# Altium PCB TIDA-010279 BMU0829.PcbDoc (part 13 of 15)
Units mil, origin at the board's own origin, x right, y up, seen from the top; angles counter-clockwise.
Board outline 11269.69 x 4438.98 mil, 4 copper layers (Top Layer, Signal Layer 1, Signal Layer 2, Bottom Layer), stack 61.6 mil thick; 1494 components, 725 nets, 3766 pads, 2728 vias.
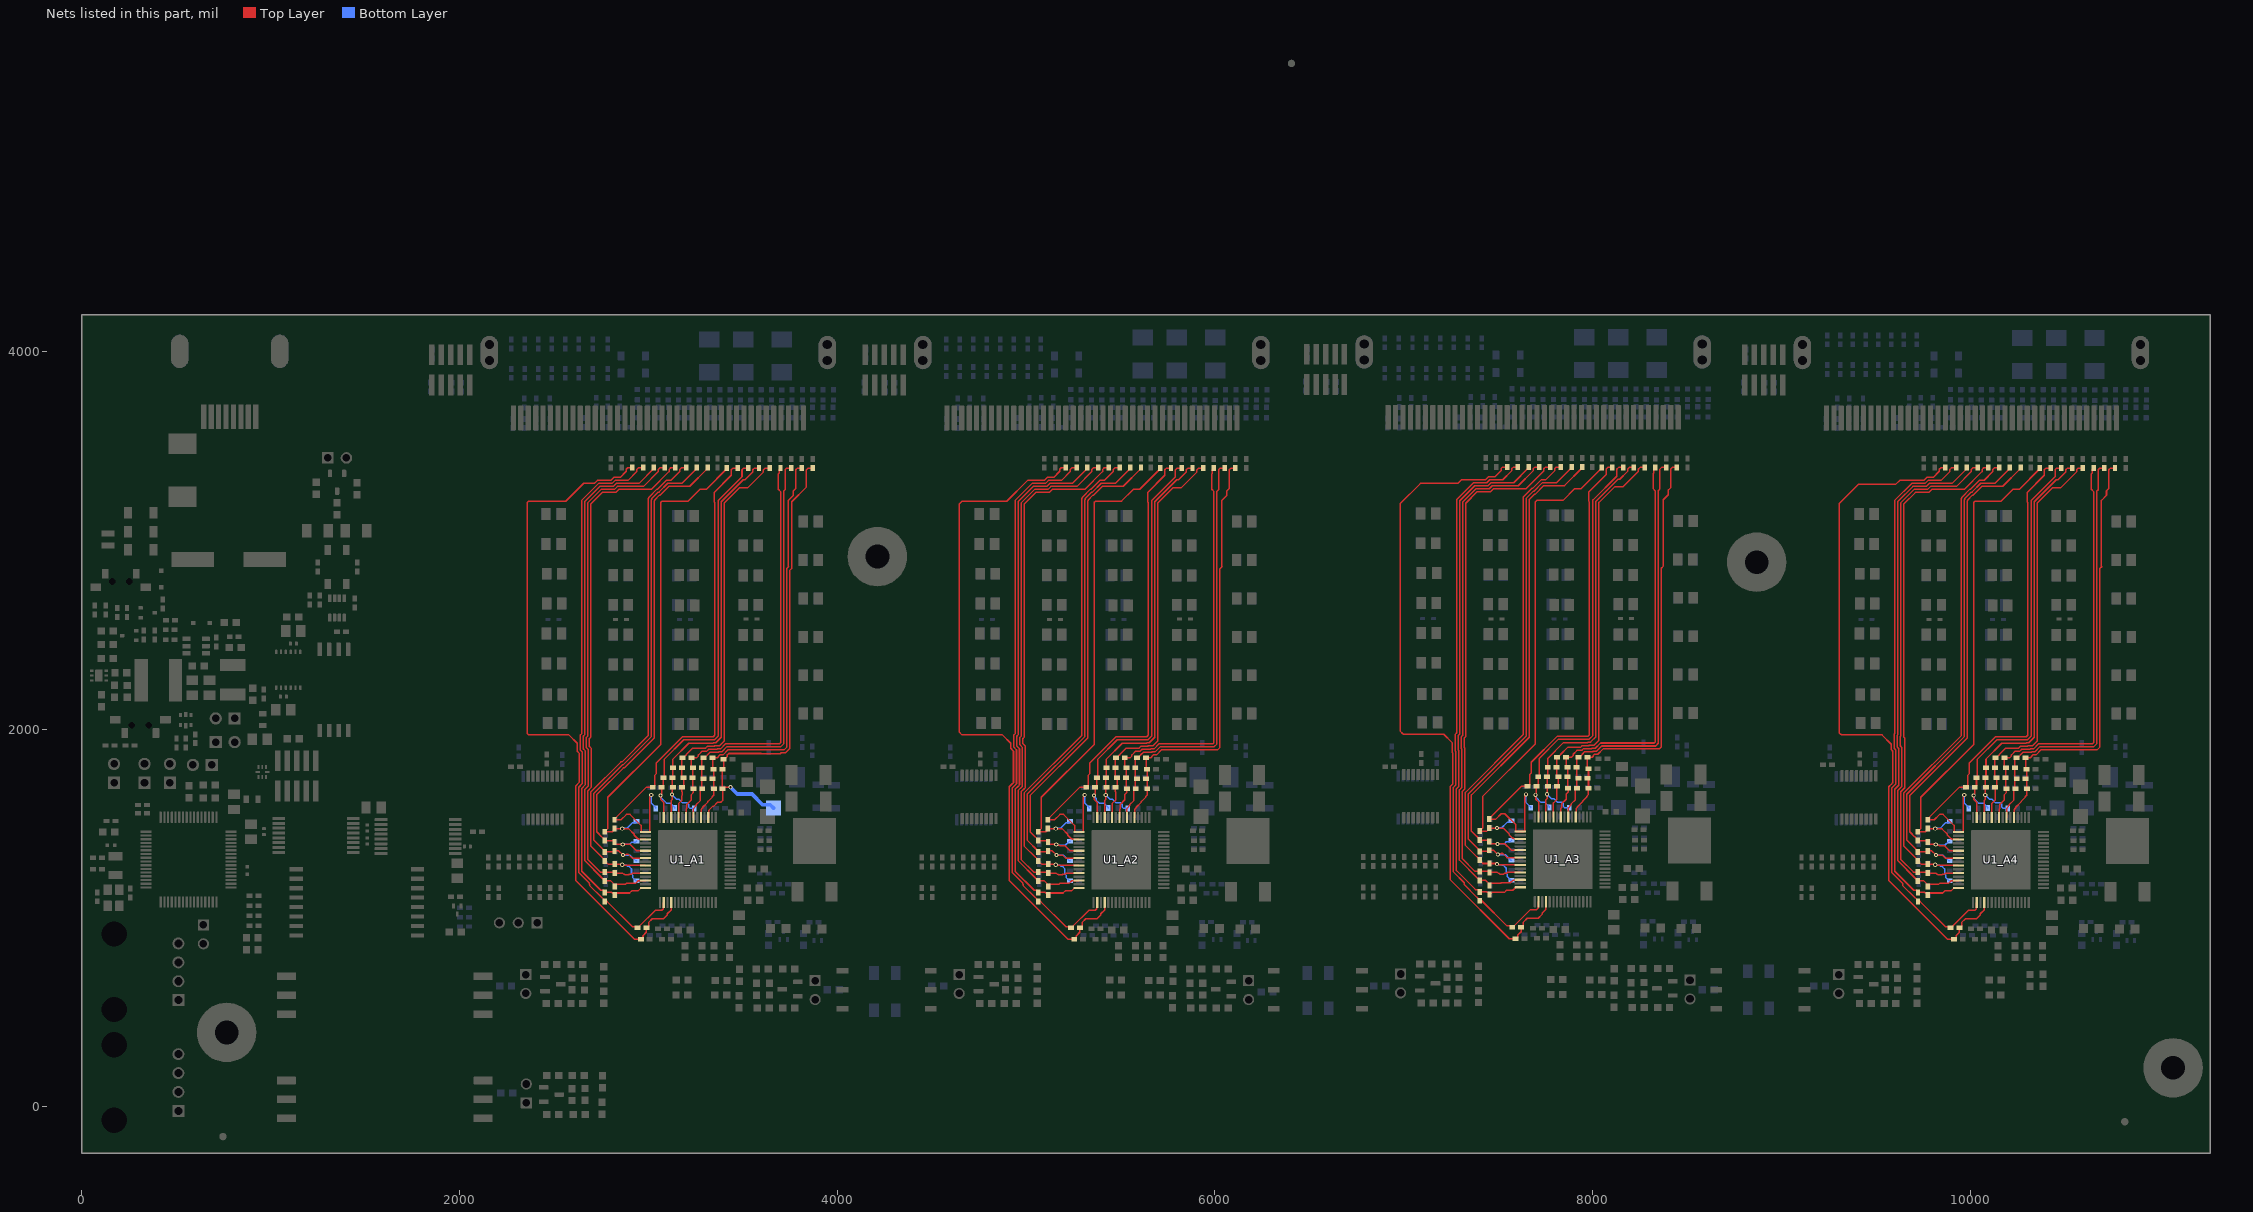
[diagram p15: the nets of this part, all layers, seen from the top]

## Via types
v1: diameter 22.01, hole 12.01, Top Layer to Bottom Layer, tented both sides, 2578 vias
v2: diameter 19.68, hole 7.87, Top Layer to Bottom Layer, tented both sides, 144 vias
v3: diameter 92.52, hole 49.21, Top Layer to Bottom Layer, 4 vias
v4: diameter 19.68, hole 7.87, Top Layer to Bottom Layer, 2 vias

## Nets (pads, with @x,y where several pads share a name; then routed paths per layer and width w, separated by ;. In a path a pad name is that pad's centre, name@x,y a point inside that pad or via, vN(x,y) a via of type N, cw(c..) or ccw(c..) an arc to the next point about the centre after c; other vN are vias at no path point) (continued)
VC2_A1: C104_A1.2 C105_A1.1 R135_A1.2 U1_A1.36 | length 3663.8
  Top Layer w8: R135_A1.2@2915.31,3384.01 2891.5,3384.01 2883.33,3375.85 2883.33,3364.55 2851.42,3332.64 2817,3332.64 2801.13,3316.77 2730.13,3316.77 2714.43,3301.07 2657.48,3301.07 2562.88,3206.46 2365.95,3206.46 2359,3199.51 2359,3002.59 2358.99,1976.1 2366.15,1968.94 2579.82,1968.94 2623.51,1925.25 2623.51,1882.87 2633.36,1873.02 2633.36,1717.29 2615.26,1699.19 2615.26,1198.42 2926.49,887.19 C105_A1.1@2952.76,887.19 ; C105_A1.1@2952.76,885.83 2962.54,885.83 2971.72,895 2971.72,906.42 2989.45,924.15 C104_A1.2@2989.45,947.96 2993.39,947.96 3001.2,955.77 3001.2,975.34 3021.25,995.39 3079.89,995.39 3100.39,1015.88 3100.39,1022.22 3120.88,1042.72 U1_A1.36@3120.88,1082.55 ; C105_A1.1@2959.97,887.19 C105_A1.1@2961.33,885.83
VC2_A2: C104_A2.2 C105_A2.1 R135_A2.2 U1_A2.36 | length 3674.9
  Top Layer w8: R135_A2.2@5210.32,3384.01 5186.51,3384.01 5178.35,3375.85 5178.35,3364.55 5146.44,3332.64 5112.02,3332.64 5096.15,3316.77 5008.13,3316.77 4897.83,3206.46 4660.97,3206.46 4645.67,3191.16 4645.67,1984.43 4661.17,1968.94 4874.84,1968.94 4918.53,1925.25 4918.53,1898.02 4933.32,1883.23 4933.32,1717.21 4926.66,1710.55 4910.28,1694.16 4910.28,1198.42 5221.51,887.19 C105_A2.1@5247.77,887.19 ; C105_A2.1@5247.77,885.83 5257.56,885.83 5266.73,895 5266.73,906.42 5284.47,924.15 C104_A2.2@5284.47,947.96 5288.4,947.96 5296.22,955.77 5296.22,975.34 5316.27,995.39 5374.91,995.39 5395.4,1015.88 5395.4,1022.22 5415.9,1042.72 U1_A2.36@5415.9,1082.55 ; C105_A2.1@5254.99,887.19 C105_A2.1@5256.35,885.83
VC2_A3: C104_A3.2 C105_A3.1 R135_A3.2 U1_A3.36 | length 3664.9
  Top Layer w8: R135_A3.2@7546.92,3387.22 7523.11,3387.22 7514.95,3379.06 7514.95,3367.76 7483.04,3335.85 7448.62,3335.85 7432.74,3319.98 7304.79,3319.98 7285.16,3300.34 7087.72,3300.34 6980.2,3192.82 6980.2,1989.64 6993.96,1975.87 6994.04,1975.87 6997.76,1972.15 7211.44,1972.15 7255.12,1928.46 7255.12,1877.23 7259.34,1873.02 7259.34,1709.84 7246.87,1697.37 7246.87,1201.63 7558.1,890.4 C105_A3.1@7591.58,890.4 ; C105_A3.1@7592.94,889.04 7594.16,889.04 7603.33,898.21 7603.33,909.63 7621.06,927.36 C104_A3.2@7621.06,951.17 7625,951.17 7632.81,958.98 7632.81,978.54 7652.86,998.6 7711.51,998.6 7732,1019.09 7732,1025.43 7752.5,1045.93 U1_A3.36@7752.5,1085.75
VC2_A4: C104_A4.2 C105_A4.1 R135_A4.2 U1_A4.36 | length 3671.6
  Top Layer w8: R135_A4.2@9867.15,3384.01 9843.34,3384.01 9835.18,3375.85 9835.18,3364.55 9803.27,3332.64 9768.85,3332.64 9752.97,3316.77 9625.02,3316.77 9605.39,3297.13 9407.95,3297.13 9306.5,3195.69 9306.5,1978.99 9312.83,1972.67 9314.27,1972.67 9317.99,1968.94 9531.67,1968.94 9580.35,1920.26 9580.35,1891.72 9588.83,1883.23 9588.83,1715.9 9582.17,1709.23 9567.1,1694.16 9567.1,1198.42 9878.33,887.19 C105_A4.1@9904.6,887.19 ; C105_A4.1@9904.6,885.83 9914.39,885.83 9923.56,895 9923.56,906.42 9941.29,924.15 C104_A4.2@9941.29,947.96 9945.23,947.96 9953.04,955.77 9953.04,975.34 9973.09,995.39 10031.74,995.39 10052.23,1015.88 10052.23,1022.22 10072.73,1042.72 U1_A4.36@10072.73,1082.55 ; C105_A4.1@9911.81,887.19 C105_A4.1@9913.17,885.83
VC3_A1: C102_A1.2 C104_A1.1 R132_A1.2 U1_A1.34 | length 3044.7
  Top Layer w8: C102_A1.2@2772.92,1088 C102_A1.2@2770.21,1088 2770.21,1091.94 2754.53,1107.63 2753.48,1107.63 2688.89,1172.22 2688.89,1177.63 2688.3,1178.22 2688.3,1183.75 2631.13,1240.91 2631.13,1692.61 2649.24,1710.71 2649.24,1879.59 2639.39,1889.44 2639.39,1968.21 2648.46,1977.29 2648.46,3212.66 2736.7,3300.89 2807.71,3300.89 2823.58,3316.77 2892.42,3316.77 2938.99,3363.35 2938.99,3374.64 2948.37,3384.01 R132_A1.2@2972.18,3384.01 ; C102_A1.2@2772.92,1090.71 2775.81,1087.81 2781.34,1087.81 2914.46,954.69 2935.48,954.69 C104_A1.1@2942.21,947.96 2946.14,947.96 2953.95,955.77 2953.95,956.82 3038.28,1041.14 3071.51,1041.14 3079.61,1049.24 3079.61,1080.64 U1_A1.34@3081.51,1082.55
VC3_A2: C102_A2.2 C104_A2.1 R132_A2.2 U1_A2.34 | length 3047.7
  Top Layer w8: R132_A2.2@5267.19,3384.01 5243.38,3384.01 5234.01,3374.64 5234.01,3363.35 5187.43,3316.77 5118.6,3316.77 5102.72,3300.89 5031.72,3300.89 4943.48,3212.66 4943.48,1977.29 4934.4,1968.21 4934.4,1904.6 4949.2,1889.8 4949.2,1710.64 4942.54,1703.98 4926.15,1687.59 4926.15,1240.91 4983.31,1183.75 4983.31,1178.22 4983.9,1177.63 4983.9,1172.22 5048.5,1107.63 5049.54,1107.63 5065.23,1091.94 C102_A2.2@5065.23,1088 5065.42,1087.81 5076.36,1087.81 5209.47,954.69 5230.49,954.69 C104_A2.1@5237.22,947.96 5241.16,947.96 5248.97,955.77 5248.97,956.82 5333.3,1041.14 5366.53,1041.14 5374.63,1049.24 5374.63,1080.64 U1_A2.34@5376.53,1082.55
VC3_A3: C102_A3.2 C104_A3.1 R132_A3.2 U1_A3.34 | length 3040
  Top Layer w8: C102_A3.2@7404.53,1091.21 C102_A3.2@7401.82,1091.21 7401.82,1095.15 7386.14,1110.83 7385.09,1110.83 7320.5,1175.43 7320.5,1180.84 7319.91,1181.43 7319.91,1186.96 7262.75,1244.12 7262.75,1690.8 7275.21,1703.26 7275.21,1879.59 7271,1883.8 7271,1971.42 7280.08,1980.5 7280.08,3215.86 7368.32,3304.1 7439.32,3304.1 7455.19,3319.98 7524.03,3319.98 7570.61,3366.55 7570.61,3377.85 7579.98,3387.22 R132_A3.2@7603.79,3387.22 ; C102_A3.2@7404.53,1093.92 7407.43,1091.02 7412.95,1091.02 7546.07,957.9 7567.09,957.9 C104_A3.1@7573.82,951.17 7577.76,951.17 7585.57,958.98 7585.57,960.03 7669.89,1044.35 7703.12,1044.35 7711.22,1052.45 7711.22,1083.85 U1_A3.34@7713.13,1085.75
VC3_A4: C102_A4.2 C104_A4.1 R132_A4.2 U1_A4.34 | length 3042.4
  Top Layer w8: R132_A4.2@9924.02,3384.01 9900.21,3384.01 9890.84,3374.64 9890.84,3363.35 9844.26,3316.77 9775.42,3316.77 9759.55,3300.89 9688.55,3300.89 9600.31,3212.66 9600.31,1977.29 9596.22,1973.21 9596.22,1898.29 9604.71,1889.8 9604.71,1709.32 9582.98,1687.59 9582.98,1240.91 9640.14,1183.75 9640.14,1178.22 9640.73,1177.63 9640.73,1172.22 9705.32,1107.63 9706.37,1107.63 9722.05,1091.94 C102_A4.2@9722.05,1088 9722.25,1087.81 9733.18,1087.81 9866.3,954.69 9887.32,954.69 C104_A4.1@9894.05,947.96 9897.99,947.96 9905.8,955.77 9905.8,956.82 9990.12,1041.14 10023.35,1041.14 10031.45,1049.24 10031.45,1080.64 U1_A4.34@10033.36,1082.55
VC4_A1: C101_A1.2 C102_A1.1 R128_A1.2 U1_A1.32 | length 2819.9
  Top Layer w8: C101_A1.2@2821.79,1120.47 2821.79,1124.4 2813.97,1132.21 2810.04,1132.21 2807.2,1135.05 2770.4,1135.05 C102_A1.1@2770.21,1135.25 2770.21,1138.99 2762.4,1146.8 2747.69,1146.8 2647.01,1247.49 2647.01,1686.04 2665.11,1704.14 2665.11,1886.17 2655.26,1896.02 2655.26,1961.64 2664.34,1970.72 2664.34,3206.08 2743.28,3285.02 2814.28,3285.02 2830.15,3300.89 2949.86,3300.89 3029.04,3380.08 R128_A1.2@3029.04,3384.01 ; C101_A1.2@2826.12,1124.4 2833.93,1132.21 2900.97,1132.21 2911.82,1143.06 2945.18,1143.06 2961.44,1159.32 U1_A1.32@2985.06,1159.32
VC4_A2: C101_A2.2 C102_A2.1 R128_A2.2 U1_A2.32 | length 2824
  Top Layer w8: C101_A2.2@5116.8,1120.47 5116.8,1124.4 5108.99,1132.21 5105.05,1132.21 5102.21,1135.05 5065.42,1135.05 C102_A2.1@5065.23,1135.25 5065.23,1138.99 5057.42,1146.8 5042.71,1146.8 4942.02,1247.49 4942.02,1681.01 4958.41,1697.4 4965.07,1704.06 4965.07,1896.38 4950.28,1911.17 4950.28,1961.64 4959.35,1970.72 4959.35,3206.08 5038.29,3285.02 5109.3,3285.02 5125.17,3300.89 5244.88,3300.89 5324.06,3380.08 R128_A2.2@5324.06,3384.01 ; C101_A2.2@5121.14,1124.4 5128.95,1132.21 5195.98,1132.21 5206.83,1143.06 5240.2,1143.06 5256.45,1159.32 U1_A2.32@5280.07,1159.32
VC4_A3: C101_A3.2 C102_A3.1 R128_A3.2 U1_A3.32 | length 2815.3
  Top Layer w8: C101_A3.2@7453.4,1123.67 7453.4,1127.61 7445.59,1135.42 7441.65,1135.42 7438.81,1138.26 7402.02,1138.26 C102_A3.1@7401.82,1138.46 7401.82,1142.2 7394.01,1150.01 7379.3,1150.01 7278.62,1250.69 7278.62,1684.22 7291.08,1696.69 7291.08,1886.17 7286.87,1890.38 7286.87,1964.85 7295.95,1973.93 7295.95,3209.29 7374.89,3288.23 7445.89,3288.23 7461.77,3304.1 7581.48,3304.1 7660.66,3383.28 R128_A3.2@7660.66,3387.22 ; C101_A3.2@7457.73,1127.61 7465.54,1135.42 7532.58,1135.42 7543.43,1146.27 7576.79,1146.27 7593.05,1162.53 U1_A3.32@7616.67,1162.53
VC4_A4: C101_A4.2 C102_A4.1 R128_A4.2 U1_A4.32 | length 2818.8
  Top Layer w8: C101_A4.2@9773.63,1120.47 9773.63,1124.4 9765.82,1132.21 9761.88,1132.21 9759.04,1135.05 9722.25,1135.05 C102_A4.1@9722.05,1135.25 9722.05,1138.99 9714.24,1146.8 9699.53,1146.8 9598.85,1247.49 9598.85,1681.01 9620.58,1702.75 9620.58,1896.38 9612.09,1904.87 9612.09,1966.63 9616.18,1970.72 9616.18,3206.08 9695.12,3285.02 9766.12,3285.02 9782,3300.89 9901.71,3300.89 9980.89,3380.08 R128_A4.2@9980.89,3384.01 ; C101_A4.2@9777.96,1124.4 9785.77,1132.21 9852.81,1132.21 9863.66,1143.06 9897.02,1143.06 9913.28,1159.32 U1_A4.32@9936.9,1159.32
VC5_A1: C98_A1.2 C101_A1.1 R126_A1.2 U1_A1.30 | length 2792.9
  Top Layer w8: U1_A1.30@2985.06,1198.69 2983.15,1196.78 2946.16,1196.78 2932.19,1182.81 2884.36,1182.81 2881,1179.46 2829.6,1179.46 2826.12,1175.98 2826.12,1171.65 2823.95,1173.81 2801.95,1195.81 C98_A1.2@2769.59,1195.81 2769.59,1199.75 2761.78,1207.56 2758.83,1207.56 2662.88,1303.51 2662.88,1679.46 2680.98,1697.56 2680.98,1892.74 2671.13,1902.59 2671.13,1955.06 2680.21,1964.14 2680.21,3199.51 2749.85,3269.15 2820.86,3269.15 2836.73,3285.02 2974.4,3285.02 3052.73,3363.35 3052.73,3374.64 3062.1,3384.01 R126_A1.2@3085.91,3384.01
VC5_A2: C98_A2.2 C101_A2.1 R126_A2.2 U1_A2.30 | length 2797
  Top Layer w8: U1_A2.30@5280.07,1198.69 5278.17,1196.78 5241.18,1196.78 5227.21,1182.81 5179.38,1182.81 5176.02,1179.46 5124.61,1179.46 5121.14,1175.98 5121.14,1171.65 5118.97,1173.81 5096.97,1195.81 C98_A2.2@5064.61,1195.81 5064.61,1199.75 5056.8,1207.56 5053.84,1207.56 4957.9,1303.51 4957.9,1674.44 4974.29,1690.83 4980.94,1697.49 4980.94,1902.95 4966.15,1917.75 4966.15,1955.06 4975.23,1964.14 4975.23,3199.51 5044.87,3269.15 5115.87,3269.15 5131.75,3285.02 5269.42,3285.02 5347.75,3363.35 5347.75,3374.64 5357.12,3384.01 R126_A2.2@5380.93,3384.01
VC5_A3: C98_A3.2 C101_A3.1 R126_A3.2 U1_A3.30 | length 2788.2
  Top Layer w8: U1_A3.30@7616.67,1201.9 7614.77,1199.99 7577.77,1199.99 7563.81,1186.02 7515.97,1186.02 7512.62,1182.67 7461.21,1182.67 7457.73,1179.19 7457.73,1174.85 7455.57,1177.02 7433.57,1199.02 C98_A3.2@7401.21,1199.02 7401.21,1202.96 7393.39,1210.77 7390.44,1210.77 7294.49,1306.72 7294.49,1677.65 7306.96,1690.11 7306.96,1892.74 7302.75,1896.95 7302.75,1958.27 7311.83,1967.35 7311.83,3202.71 7381.47,3272.35 7452.47,3272.35 7468.34,3288.23 7606.02,3288.23 7684.34,3366.55 7684.34,3377.85 7693.71,3387.22 R126_A3.2@7717.52,3387.22
VC5_A4: C98_A4.2 C101_A4.1 R126_A4.2 U1_A4.30 | length 2791.8
  Top Layer w8: U1_A4.30@9936.9,1198.69 9935,1196.78 9898,1196.78 9884.04,1182.81 9836.2,1182.81 9832.85,1179.46 9781.44,1179.46 9777.96,1175.98 9777.96,1171.65 9775.8,1173.81 9753.8,1195.81 C98_A4.2@9721.44,1195.81 9721.44,1199.75 9713.62,1207.56 9710.67,1207.56 9614.72,1303.51 9614.72,1674.44 9636.46,1696.17 9636.46,1902.95 9627.97,1911.44 9627.97,1960.06 9632.06,1964.14 9632.06,3199.51 9701.7,3269.15 9772.7,3269.15 9788.57,3285.02 9926.25,3285.02 10004.57,3363.35 10004.57,3374.64 10013.94,3384.01 R126_A4.2@10037.75,3384.01
VC6_A1: C88_A1.2 C98_A1.1 R114_A1.2 U1_A1.28 | length 2781.5
  Top Layer w8: U1_A1.28@2985.06,1238.06 2984.91,1237.91 2917.08,1237.91 2911.63,1232.46 2899.48,1232.46 2896.04,1229.02 2877.09,1229.02 2873.65,1232.46 2869.18,1232.46 2863.73,1237.91 C88_A1.2@2821.79,1237.91 ; R114_A1.2@3142.78,3384.01 3118.97,3384.01 3109.6,3374.64 3109.6,3363.35 3015.4,3269.15 2843.3,3269.15 2827.43,3253.27 2756.43,3253.27 2696.09,3192.93 2696.09,1957.57 2687.01,1948.49 2687.01,1909.17 2696.86,1899.32 2696.86,1690.99 2678.76,1672.89 2678.76,1310.08 2745.78,1243.06 C98_A1.1@2769.59,1243.06 C88_A1.2@2816.64,1243.06 ; C88_A1.2@2816.64,1243.06 C88_A1.2@2821.79,1237.91 ; C88_A1.2@2816.64,1243.06 C88_A1.2@2821.79,1237.91
VC6_A2: C88_A2.2 C98_A2.1 R114_A2.2 U1_A2.28 | length 2778.4
  Top Layer w8: U1_A2.28@5280.07,1238.06 5279.93,1237.91 5212.1,1237.91 5206.65,1232.46 5194.5,1232.46 5191.06,1229.02 5172.11,1229.02 5168.67,1232.46 5164.2,1232.46 5158.75,1237.91 C88_A2.2@5116.8,1237.91 5111.66,1243.06 C98_A2.1@5064.61,1243.06 5040.8,1243.06 4973.77,1310.08 4973.77,1667.86 4990.16,1684.25 4996.82,1690.91 4996.82,1909.53 4982.02,1924.32 4982.02,1948.49 4991.1,1957.57 4991.1,3192.93 5051.44,3253.27 5122.45,3253.27 5138.32,3269.15 5310.41,3269.15 5404.61,3363.35 5404.61,3374.64 5413.98,3384.01 R114_A2.2@5437.8,3384.01
VC6_A3: C88_A3.2 C98_A3.1 R114_A3.2 U1_A3.28 | length 2776.9
  Top Layer w8: U1_A3.28@7616.67,1241.27 7616.52,1241.12 7548.69,1241.12 7543.24,1235.67 7531.09,1235.67 7527.66,1232.23 7508.7,1232.23 7505.26,1235.67 7500.79,1235.67 7495.34,1241.12 C88_A3.2@7453.4,1241.12 ; R114_A3.2@7774.39,3387.22 7750.58,3387.22 7741.21,3377.85 7741.21,3366.55 7647.01,3272.35 7474.92,3272.35 7459.04,3256.48 7388.04,3256.48 7327.7,3196.14 7327.7,1960.78 7318.62,1951.7 7318.62,1903.53 7322.83,1899.32 7322.83,1683.54 7310.37,1671.07 7310.37,1313.29 7377.39,1246.27 C98_A3.1@7401.21,1246.27 C88_A3.2@7448.25,1246.27 ; C88_A3.2@7448.25,1246.27 C88_A3.2@7453.4,1241.12 ; C88_A3.2@7448.25,1246.27 C88_A3.2@7453.4,1241.12
VC6_A4: C88_A4.2 C98_A4.1 R114_A4.2 U1_A4.28 | length 2769.8
  Top Layer w8: U1_A4.28@9936.9,1238.06 9936.75,1237.91 9868.92,1237.91 9863.47,1232.46 9851.32,1232.46 9847.89,1229.02 9828.93,1229.02 9825.49,1232.46 9821.02,1232.46 9815.57,1237.91 C88_A4.2@9773.63,1237.91 9768.48,1243.06 C98_A4.1@9721.44,1243.06 9697.62,1243.06 9630.6,1310.08 9630.6,1667.86 9652.33,1689.6 9652.33,1953.17 9647.93,1957.57 9647.93,3192.93 9708.27,3253.27 9779.27,3253.27 9795.15,3269.15 9967.24,3269.15 10061.44,3363.35 10061.44,3374.64 10070.81,3384.01 R114_A4.2@10094.62,3384.01
VC7_A1: C81_A1.2 C88_A1.1 C96_A1.1 R104_A1.2 U1_A1.26 | length 2718.7
  Top Layer w8: U1_A1.26@2985.06,1277.43 2984.27,1278.22 2865.19,1278.22 v1(2861.72,1281.69) 2858.25,1285.15 C88_A1.1@2821.79,1285.15 2787.26,1285.15 2781.59,1290.82 2777.66,1290.82 2769.85,1298.63 C81_A1.2@2769.85,1302.57 2769.85,1306.51 2754.16,1322.19 2753.12,1322.19 2694.63,1380.68 2694.63,1666.31 2854.78,1826.46 2859.81,1826.46 2999.93,1966.59 2999.93,3220.93 3001.79,3222.79 3001.79,3226.76 3045.94,3270.91 3049.9,3270.91 3096.48,3317.48 3120.6,3317.48 3166.46,3363.35 3166.46,3374.64 3175.84,3384.01 R104_A1.2@3199.65,3384.01
  Bottom Layer w8: v1(2861.72,1281.69) 2864.4,1279.01 2883.57,1279.01 2887.8,1274.78 2896.04,1274.78 2910.85,1259.97 2910.85,1232.65 2916.71,1226.79 2916.71,1214.61 2934.54,1196.78 C96_A1.1@2938.47,1196.78
VC7_A2: C81_A2.2 C88_A2.1 C96_A2.1 R104_A2.2 U1_A2.26 | length 2715.8
  Top Layer w8: U1_A2.26@5280.07,1277.43 5279.29,1278.22 5160.2,1278.22 v1(5156.73,1281.69) 5153.26,1285.15 C88_A2.1@5116.8,1285.15 5082.28,1285.15 5076.61,1290.82 5072.67,1290.82 5064.86,1298.63 C81_A2.2@5064.86,1302.57 5064.86,1306.51 5049.18,1322.19 5048.13,1322.19 4989.65,1380.68 4989.65,1661.29 5294.94,1966.59 5294.94,3220.93 5296.8,3222.79 5296.8,3226.76 5340.95,3270.91 5344.92,3270.91 5391.49,3317.48 5415.62,3317.48 5461.48,3363.35 5461.48,3374.64 5470.85,3384.01 R104_A2.2@5494.66,3384.01
  Bottom Layer w8: v1(5156.73,1281.69) 5159.41,1279.01 5178.59,1279.01 5182.81,1274.78 5191.06,1274.78 5205.87,1259.97 5205.87,1232.65 5211.73,1226.79 5211.73,1214.61 5229.55,1196.78 C96_A2.1@5233.49,1196.78
VC7_A3: C81_A3.2 C88_A3.1 C96_A3.1 R104_A3.2 U1_A3.26 | length 2715.8
  Top Layer w8: U1_A3.26@7616.67,1280.64 7615.88,1281.42 7496.8,1281.42 v1(7493.33,1284.89) 7489.86,1288.36 C88_A3.1@7453.4,1288.36 7418.87,1288.36 7413.21,1294.03 7409.27,1294.03 7401.46,1301.84 C81_A3.2@7401.46,1305.78 7401.46,1309.72 7385.77,1325.4 7384.73,1325.4 7326.24,1383.89 7326.24,1664.5 7631.54,1969.79 7631.54,3224.14 7633.4,3226 7633.4,3229.97 7677.55,3274.12 7681.52,3274.12 7728.09,3320.69 7752.21,3320.69 7798.08,3366.55 7798.08,3377.85 7807.45,3387.22 R104_A3.2@7831.26,3387.22
  Bottom Layer w8: v1(7493.33,1284.89) 7496.01,1282.21 7515.18,1282.21 7519.41,1277.99 7527.66,1277.99 7542.46,1263.18 7542.46,1235.86 7548.33,1230 7548.33,1217.81 7566.15,1199.99 C96_A3.1@7570.09,1199.99
VC7_A4: C81_A4.2 C88_A4.1 C96_A4.1 R104_A4.2 U1_A4.26 | length 2715.8
  Top Layer w8: U1_A4.26@9936.9,1277.43 9936.11,1278.22 9817.03,1278.22 v1(9813.56,1281.69) 9810.09,1285.15 C88_A4.1@9773.63,1285.15 9739.1,1285.15 9733.44,1290.82 9729.5,1290.82 9721.69,1298.63 C81_A4.2@9721.69,1302.57 9721.69,1306.51 9706,1322.19 9704.96,1322.19 9646.47,1380.68 9646.47,1661.29 9951.77,1966.59 9951.77,3220.93 9953.63,3222.79 9953.63,3226.76 9997.78,3270.91 10001.75,3270.91 10048.32,3317.48 10072.44,3317.48 10118.31,3363.35 10118.31,3374.64 10127.68,3384.01 R104_A4.2@10151.49,3384.01
  Bottom Layer w8: v1(9813.56,1281.69) 9816.24,1279.01 9835.41,1279.01 9839.64,1274.78 9847.89,1274.78 9862.69,1259.97 9862.69,1232.65 9868.56,1226.79 9868.56,1214.61 9886.38,1196.78 C96_A4.1@9890.32,1196.78
VC8_A1: C71_A1.2 C81_A1.1 C89_A1.1 R100_A1.2 U1_A1.24 | length 2657.2
  Top Layer w8: U1_A1.24@2985.06,1316.8 2914.34,1316.8 2893.03,1338.11 2885.03,1338.11 2882.44,1335.53 2868.7,1335.53 v1(2866.02,1332.84) 2843.59,1355.28 2820.95,1355.28 C71_A1.2@2820.87,1355.36 2815.33,1349.81 C81_A1.1@2769.85,1349.81 2769.85,1353.75 2710.5,1413.09 2710.5,1659.74 2861.36,1810.59 2866.38,1810.59 3016.19,1960.4 3016.19,3214.75 3017.66,3216.22 3017.66,3220.18 3052.51,3255.03 3056.48,3255.03 3103.05,3301.61 3178.05,3301.61 3256.52,3380.08 R100_A1.2@3256.52,3384.01
  Bottom Layer w8: v1(2866.02,1332.84) 2867.63,1331.23 2905.28,1331.23 2934.54,1301.98 C89_A1.1@2938.47,1301.98
VC8_A2: C71_A2.2 C81_A2.1 C89_A2.1 R100_A2.2 U1_A2.24 | length 2657.8
  Top Layer w8: U1_A2.24@5280.07,1316.8 5209.35,1316.8 5193.31,1332.84 v1(5161.04,1332.84) 5138.6,1355.28 5115.97,1355.28 C71_A2.2@5115.89,1355.36 ; R100_A2.2@5551.53,3384.01 5551.53,3380.08 5473.06,3301.61 5398.07,3301.61 5351.5,3255.03 5347.53,3255.03 5312.68,3220.18 5312.68,3216.22 5311.21,3214.75 5311.21,1960.4 5005.52,1654.71 5005.52,1413.09 5064.86,1353.75 C81_A2.1@5064.86,1349.81 C71_A2.2@5110.35,1349.81 ; C71_A2.2@5110.35,1349.81 C71_A2.2@5115.89,1355.36 ; C71_A2.2@5110.35,1349.81 C71_A2.2@5115.89,1355.36
  Bottom Layer w8: v1(5161.04,1332.84) 5162.65,1331.23 5200.3,1331.23 5229.55,1301.98 C89_A2.1@5233.49,1301.98
VC8_A3: C71_A3.2 C81_A3.1 C89_A3.1 R100_A3.2 U1_A3.24 | length 2662.1
  Top Layer w8: U1_A3.24@7616.67,1320.01 7545.95,1320.01 7524.64,1341.32 7516.64,1341.32 7514.05,1338.73 7500.31,1338.73 v1(7497.63,1336.05) 7475.2,1358.49 7452.56,1358.49 C71_A3.2@7452.48,1358.56 ; R100_A3.2@7888.13,3387.22 7888.13,3383.28 7809.66,3304.82 7734.67,3304.82 7688.09,3258.24 7684.13,3258.24 7649.27,3223.39 7649.27,3219.42 7647.81,3217.96 7647.81,1963.61 7342.12,1657.92 7342.12,1416.3 7401.46,1356.96 C81_A3.1@7401.46,1353.02 C71_A3.2@7446.94,1353.02 ; C71_A3.2@7446.94,1353.02 C71_A3.2@7452.48,1358.56 ; C71_A3.2@7446.94,1353.02 C71_A3.2@7452.48,1358.56
  Bottom Layer w8: v1(7497.63,1336.05) 7499.25,1334.44 7536.89,1334.44 7566.15,1305.18 C89_A3.1@7570.09,1305.18
VC8_A4: C71_A4.2 C81_A4.1 C89_A4.1 R100_A4.2 U1_A4.24 | length 2657.8
  Top Layer w8: U1_A4.24@9936.9,1316.8 9866.18,1316.8 9850.13,1332.84 v1(9817.86,1332.84) 9795.43,1355.28 9772.79,1355.28 C71_A4.2@9772.71,1355.36 ; R100_A4.2@10208.36,3384.01 10208.36,3380.08 10129.89,3301.61 10054.9,3301.61 10008.32,3255.03 10004.36,3255.03 9969.5,3220.18 9969.5,3216.22 9968.04,3214.75 9968.04,1960.4 9662.35,1654.71 9662.35,1413.09 9721.69,1353.75 C81_A4.1@9721.69,1349.81 C71_A4.2@9767.17,1349.81 ; C71_A4.2@9767.17,1349.81 C71_A4.2@9772.71,1355.36 ; C71_A4.2@9767.17,1349.81 C71_A4.2@9772.71,1355.36
  Bottom Layer w8: v1(9817.86,1332.84) 9819.48,1331.23 9857.12,1331.23 9886.38,1301.98 C89_A4.1@9890.32,1301.98
VC9_A1: C63_A1.2 C71_A1.1 C84_A1.1 R90_A1.2 U1_A1.22 | length 2627.6
  Top Layer w8: C71_A1.1@2820.87,1402.6 2819.02,1404.45 2814.14,1409.33 C63_A1.2@2770.09,1409.33 2770.09,1413.26 2754.41,1428.95 2753.36,1428.95 2726.38,1455.94 2726.38,1653.16 2867.93,1794.72 2872.96,1794.72 3032.07,1953.83 3032.07,3208.17 3033.54,3209.64 3033.54,3213.61 3059.09,3239.16 3063.06,3239.16 3109.63,3285.73 3219.04,3285.73 3313.38,3380.08 R90_A1.2@3313.38,3384.01 ; C71_A1.1@2821.61,1402.6 2821.61,1397.92 2828.68,1390.85 2861.95,1390.85 v1(2864.4,1388.41) ; v1@2864.4,1389.66 2864.83,1390.1 2903.02,1390.1 2936.95,1356.17 U1_A1.22@2985.06,1356.17
  Bottom Layer w8: v1(2864.4,1388.41) 2866.09,1390.1 2900.98,1390.1 2904.67,1393.79 ; 2904.71,1393.79 2910.73,1399.8 2931.1,1399.8 C84_A1.1@2938.47,1407.17
VC9_A2: C63_A2.2 C71_A2.1 C84_A2.1 R90_A2.2 U1_A2.22 | length 2652
  Top Layer w8: C71_A2.1@5116.63,1402.6 5116.63,1397.92 C71_A2.1@5123.7,1390.85 ; v1(5159.41,1388.41) 5156.97,1390.85 C71_A2.1@5123.7,1390.85 ; v1@5159.41,1389.66 5163.35,1385.73 5176.39,1385.73 5180.98,1381.14 5206.99,1381.14 5231.96,1356.17 U1_A2.22@5280.07,1356.17 ; R90_A2.2@5608.4,3384.01 5608.4,3380.08 5514.06,3285.73 5404.64,3285.73 5358.07,3239.16 5354.11,3239.16 5328.55,3213.61 5328.55,3209.64 5327.08,3208.17 5327.08,1953.83 5021.39,1648.14 5021.39,1455.94 5048.38,1428.95 5049.43,1428.95 5065.11,1413.26 C63_A2.2@5065.11,1409.33 C71_A2.1@5109.16,1409.33 ; C71_A2.1@5109.16,1409.33 C71_A2.1@5115.89,1402.6 ; C71_A2.1@5109.16,1409.33 5114.03,1404.45 C71_A2.1@5115.89,1402.6 ; C71_A2.1@5115.89,1402.6 5115.89,1398.66 C71_A2.1@5123.7,1390.85
  Bottom Layer w8: v1(5159.41,1388.41) 5163.2,1388.41 5167.01,1384.6 5206.98,1384.6 5229.55,1407.17 C84_A2.1@5233.49,1407.17
VC9_A3: C63_A3.2 C71_A3.1 C84_A3.1 R90_A3.2 U1_A3.22 | length 2634.2
  Top Layer w8: C71_A3.1@7453.23,1405.81 7453.23,1401.13 7460.29,1394.06 7493.56,1394.06 v1(7496.01,1391.62) ; v1@7496.01,1392.87 7496.44,1393.31 7534.63,1393.31 7568.56,1359.38 U1_A3.22@7616.67,1359.38 ; R90_A3.2@7945,3387.22 7945,3383.28 7850.65,3288.94 7741.24,3288.94 7694.67,3242.37 7690.7,3242.37 7665.15,3216.81 7665.15,3212.85 7663.68,3211.38 7663.68,1957.04 7357.99,1651.35 7357.99,1459.14 7384.98,1432.16 7386.02,1432.16 7401.71,1416.47 C63_A3.2@7401.71,1412.54 C71_A3.1@7445.76,1412.54 ; C71_A3.1@7445.76,1412.54 C71_A3.1@7452.48,1405.81 7450.63,1407.66 C71_A3.1@7445.76,1412.54
  Bottom Layer w8: v1(7496.01,1391.62) 7497.7,1393.31 7532.59,1393.31 7536.28,1397 ; 7536.33,1397 7542.34,1403.01 7562.72,1403.01 C84_A3.1@7570.09,1410.38
VC9_A4: C63_A4.2 C71_A4.1 C84_A4.1 R90_A4.2 U1_A4.22 | length 2652
  Top Layer w8: C71_A4.1@9773.46,1402.6 9773.46,1397.92 C71_A4.1@9780.52,1390.85 ; v1(9816.24,1388.41) 9813.79,1390.85 C71_A4.1@9780.52,1390.85 ; v1@9816.24,1389.66 9820.18,1385.73 9831.9,1385.73 9836.48,1381.14 9863.81,1381.14 9888.79,1356.17 U1_A4.22@9936.9,1356.17 ; R90_A4.2@10265.23,3384.01 10265.23,3380.08 10170.88,3285.73 10061.47,3285.73 10014.9,3239.16 10010.93,3239.16 9985.38,3213.61 9985.38,3209.64 9983.91,3208.17 9983.91,1953.83 9678.22,1648.14 9678.22,1455.94 9705.21,1428.95 9706.25,1428.95 9721.94,1413.26 C63_A4.2@9721.94,1409.33 C71_A4.1@9765.99,1409.33 ; C71_A4.1@9765.99,1409.33 C71_A4.1@9772.71,1402.6 ; C71_A4.1@9765.99,1409.33 9770.86,1404.45 C71_A4.1@9772.71,1402.6 ; C71_A4.1@9772.71,1402.6 9772.71,1398.66 C71_A4.1@9780.52,1390.85
  Bottom Layer w8: v1(9816.24,1388.41) 9820.03,1388.41 9823.84,1384.6 9863.81,1384.6 9886.38,1407.17 C84_A4.1@9890.32,1407.17
VC10_A1: C58_A1.2 C63_A1.1 C79_A1.1 R83_A1.2 U1_A1.19 | length 2638
  Top Layer w8: U1_A1.19@2985.06,1415.22 2983.15,1417.13 2950.15,1417.13 2948.34,1418.94 2944.35,1418.94 2925.78,1437.51 2925.78,1442.85 2897.53,1471.11 2864.87,1471.11 2863.18,1472.8 v1(2861.72,1472.8) C58_A1.2@2820.86,1472.8 2820.86,1468.86 2808.57,1456.57 C63_A1.1@2770.09,1456.57 2770.09,1460.51 2777.91,1468.32 2780.75,1468.32 2785.43,1473.01 2785.43,1639.27 3065.28,1919.12 3065.28,3200.46 3072.24,3207.41 3210.75,3207.41 3273.2,3269.86 3307.24,3269.86 3415.33,3377.95 R83_A1.2@3415.33,3381.89
  Bottom Layer w8: v1@2863.18,1472.8 2864.65,1474.27 2886.18,1474.27 2911.23,1499.33 2911.29,1499.33 2916.52,1504.55 2930.66,1504.55 C79_A1.1@2938.47,1512.36
VC10_A2: C58_A2.2 C63_A2.1 C79_A2.1 R83_A2.2 U1_A2.19 | length 2638
  Top Layer w8: U1_A2.19@5280.07,1415.22 5278.17,1417.13 5245.16,1417.13 5243.35,1418.94 5239.37,1418.94 5220.8,1437.51 5220.8,1442.85 5192.54,1471.11 5159.89,1471.11 5158.19,1472.8 v1(5156.73,1472.8) C58_A2.2@5115.88,1472.8 5115.88,1468.86 5103.59,1456.57 C63_A2.1@5065.11,1456.57 5065.11,1460.51 5072.92,1468.32 5075.76,1468.32 5080.45,1473.01 5080.45,1639.27 5360.3,1919.12 5360.3,3200.46 5367.26,3207.41 5505.77,3207.41 5568.21,3269.86 5602.25,3269.86 5710.34,3377.95 R83_A2.2@5710.34,3381.89
  Bottom Layer w8: v1@5158.19,1472.8 5159.67,1474.27 5181.2,1474.27 5206.25,1499.33 5206.3,1499.33 5211.53,1504.55 5225.68,1504.55 C79_A2.1@5233.49,1512.36
VC10_A3: C58_A3.2 C63_A3.1 C79_A3.1 R83_A3.2 U1_A3.19 | length 2638
  Top Layer w8: U1_A3.19@7616.67,1418.43 7614.77,1420.34 7581.76,1420.34 7579.95,1422.15 7575.96,1422.15 7557.4,1440.72 7557.4,1446.06 7529.14,1474.31 7496.49,1474.31 7494.79,1476.01 v1(7493.33,1476.01) C58_A3.2@7452.48,1476.01 7452.48,1472.07 7440.18,1459.78 C63_A3.1@7401.71,1459.78 7401.71,1463.72 7409.52,1471.53 7412.36,1471.53 7417.05,1476.21 7417.05,1642.48 7696.9,1922.33 7696.9,3203.66 7703.85,3210.62 7842.36,3210.62 7904.81,3273.07 7938.85,3273.07 8046.94,3381.16 R83_A3.2@8046.94,3385.1
  Bottom Layer w8: v1@7494.79,1476.01 7496.26,1477.48 7517.79,1477.48 7542.85,1502.53 7542.9,1502.53 7548.13,1507.76 7562.28,1507.76 C79_A3.1@7570.09,1515.57
VC10_A4: C58_A4.2 C63_A4.1 C79_A4.1 R83_A4.2 U1_A4.19 | length 2638
  Top Layer w8: U1_A4.19@9936.9,1415.22 9935,1417.13 9901.99,1417.13 9900.18,1418.94 9896.19,1418.94 9877.62,1437.51 9877.62,1442.85 9849.37,1471.11 9816.72,1471.11 9815.02,1472.8 v1(9813.56,1472.8) C58_A4.2@9772.71,1472.8 9772.71,1468.86 9760.41,1456.57 C63_A4.1@9721.94,1456.57 9721.94,1460.51 9729.75,1468.32 9732.59,1468.32 9737.28,1473.01 9737.28,1639.27 10017.13,1919.12 10017.13,3200.46 10024.08,3207.41 10162.59,3207.41 10225.04,3269.86 10259.08,3269.86 10367.17,3377.95 R83_A4.2@10367.17,3381.89
  Bottom Layer w8: v1@9815.02,1472.8 9816.49,1474.27 9838.02,1474.27 9863.08,1499.33 9863.13,1499.33 9868.36,1504.55 9882.51,1504.55 C79_A4.1@9890.32,1512.36
VC11_A1: C49_A1.2 C58_A1.1 C75_A1.1 R75_A1.2 U1_A1.17 | length 2801.5
  Top Layer w8: v1(3015.04,1651.11) 3015.04,1647.32 3008.64,1640.91 3008.64,1456.5 3006.73,1454.59 U1_A1.17@2985.06,1454.59 2963.38,1454.59 2961.48,1456.5 2961.48,1490.17 2903.18,1548.47 2884.22,1548.47 2855.8,1520.04 C58_A1.1@2820.86,1520.04 2820.86,1523.98 2989.92,1693.04 C49_A1.2@3023.44,1693.04 3027.11,1693.04 3034.92,1700.85 3034.92,1756.24 3042.87,1764.19 3042.87,1821.29 3181.33,1959.75 3343.93,1959.75 3348.88,1964.69 3350.89,1966.7 3350.89,3199.79 3348.6,3202.08 3348.6,3253.2 3439.01,3343.61 3439.01,3372.52 3448.39,3381.89 R75_A1.2@3472.2,3381.89
  Bottom Layer w8: v1(3015.04,1651.11) 3015.04,1608.59 3039.3,1584.33 C75_A1.1@3039.3,1580.39
VC11_A2: C49_A2.2 C58_A2.1 C75_A2.1 R75_A2.2 U1_A2.17 | length 2801.5
  Top Layer w8: v1(5310.06,1651.11) 5310.06,1647.32 5303.65,1640.91 5303.65,1456.5 5301.75,1454.59 U1_A2.17@5280.07,1454.59 5258.4,1454.59 5256.5,1456.5 5256.5,1490.17 5198.19,1548.47 5179.24,1548.47 5150.82,1520.04 C58_A2.1@5115.88,1520.04 5115.88,1523.98 5284.93,1693.04 C49_A2.2@5318.46,1693.04 5322.13,1693.04 5329.94,1700.85 5329.94,1756.24 5337.89,1764.19 5337.89,1821.29 5476.35,1959.75 5638.95,1959.75 5643.9,1964.69 5645.91,1966.7 5645.91,3199.79 5643.61,3202.08 5643.61,3253.2 5734.03,3343.61 5734.03,3372.52 5743.4,3381.89 R75_A2.2@5767.21,3381.89
  Bottom Layer w8: v1(5310.06,1651.11) 5310.06,1608.59 5334.32,1584.33 C75_A2.1@5334.32,1580.39
VC11_A3: C49_A3.2 C58_A3.1 C75_A3.1 R75_A3.2 U1_A3.17 | length 2801.5
  Top Layer w8: v1(7646.66,1654.32) 7646.66,1650.53 7640.25,1644.12 7640.25,1459.71 7638.34,1457.8 U1_A3.17@7616.67,1457.8 7595,1457.8 7593.09,1459.71 7593.09,1493.37 7534.79,1551.68 7515.84,1551.68 7487.41,1523.25 C58_A3.1@7452.48,1523.25 7452.48,1527.19 7621.53,1696.25 C49_A3.2@7655.05,1696.25 7658.72,1696.25 7666.53,1704.06 7666.53,1759.45 7674.48,1767.4 7674.48,1824.49 7812.95,1962.96 7975.55,1962.96 7980.49,1967.9 7982.5,1969.91 7982.5,3202.99 7980.21,3205.29 7980.21,3256.4 8070.63,3346.82 8070.63,3375.73 8080,3385.1 R75_A3.2@8103.81,3385.1
  Bottom Layer w8: v1(7646.66,1654.32) 7646.66,1611.8 7670.92,1587.54 C75_A3.1@7670.92,1583.6
VC11_A4: C49_A4.2 C58_A4.1 C75_A4.1 R75_A4.2 U1_A4.17 | length 2801.5
  Top Layer w8: v1(9966.89,1651.11) 9966.89,1647.32 9960.48,1640.91 9960.48,1456.5 9958.57,1454.59 U1_A4.17@9936.9,1454.59 9915.23,1454.59 9913.32,1456.5 9913.32,1490.17 9855.02,1548.47 9836.07,1548.47 9807.64,1520.05 C58_A4.1@9772.71,1520.05 9772.71,1523.98 9941.76,1693.04 C49_A4.2@9975.28,1693.04 9978.95,1693.04 9986.76,1700.85 9986.76,1756.24 9994.71,1764.19 9994.71,1821.29 10133.18,1959.75 10295.78,1959.75 10300.72,1964.69 10302.73,1966.7 10302.73,3199.79 10300.44,3202.08 10300.44,3253.2 10390.86,3343.61 10390.86,3372.52 10400.23,3381.89 R75_A4.2@10424.04,3381.89
  Bottom Layer w8: v1(9966.89,1651.11) 9966.89,1608.59 9991.15,1584.33 C75_A4.1@9991.15,1580.39
VC12_A1: C45_A1.2 C49_A1.1 C67_A1.1 R65_A1.2 U1_A1.15 | length 2260.1
  Top Layer w8: v1(3064.83,1648.57) 3064.97,1648.43 3064.97,1628.64 3081.51,1612.09 U1_A1.15@3081.51,1531.37 ; v1@3070.42,1656.11 3070.42,1692.77 C49_A1.1@3070.69,1693.04 3072.23,1693.04 3080.04,1700.85 C45_A1.2@3080.04,1743.6 3085.2,1748.75 3085.2,1841.16 3187.91,1943.87 3350.51,1943.87 3369.75,1963.11 3369.75,3209.87 3495.88,3336.01 3495.88,3372.52 3505.25,3381.89 R65_A1.2@3529.06,3381.89
  Bottom Layer w8: v1(3064.83,1648.57) 3064.97,1648.43 3064.97,1639.41 3096.15,1608.22 3116.42,1608.22 3139.48,1585.16 C67_A1.1@3139.48,1581.22
VC12_A2: C45_A2.2 C49_A2.1 C67_A2.1 R65_A2.2 U1_A2.15 | length 2262.6
  Top Layer w8: v1(5359.84,1648.57) 5359.98,1648.43 5359.98,1628.64 5376.53,1612.09 U1_A2.15@5376.53,1531.37 ; v1@5365.43,1656.11 5365.43,1692.77 C49_A2.1@5365.7,1693.04 5367.25,1693.04 5375.06,1700.85 C45_A2.2@5375.06,1743.6 5380.21,1748.75 5380.21,1841.16 5482.93,1943.87 5645.53,1943.87 5664.76,1963.11 5664.76,3209.87 5790.9,3336.01 5790.9,3372.52 5800.27,3381.89 R65_A2.2@5824.08,3381.89
  Bottom Layer w8: v1(5359.84,1648.57) 5359.84,1644.78 5370.81,1633.81 5370.81,1624.38 5386.97,1608.22 5411.43,1608.22 5434.5,1585.16 C67_A2.1@5434.5,1581.22
VC12_A3: C45_A3.2 C49_A3.1 C67_A3.1 R65_A3.2 U1_A3.15 | length 2261
  Top Layer w8: v1(7696.44,1651.77) 7698.75,1649.47 7698.75,1628.77 7713.13,1614.39 U1_A3.15@7713.13,1534.57 ; v1@7702.03,1659.32 7702.03,1695.98 C49_A3.1@7702.3,1696.25 7703.84,1696.25 7711.66,1704.06 C45_A3.2@7711.66,1746.8 7716.81,1751.96 7716.81,1844.37 7819.52,1947.08 7982.12,1947.08 8001.36,1966.32 8001.36,3213.08 8127.49,3339.21 8127.49,3375.73 8136.87,3385.1 R65_A3.2@8160.68,3385.1
  Bottom Layer w8: v1(7696.44,1651.77) 7699.12,1649.09 7699.12,1638.58 7726.28,1611.43 7748.03,1611.43 7771.09,1588.36 C67_A3.1@7771.09,1584.43
VC12_A4: C45_A4.2 C49_A4.1 C67_A4.1 R65_A4.2 U1_A4.15 | length 2263.3
  Top Layer w8: v1(10016.67,1648.57) 10016.81,1648.43 10016.81,1628.64 10033.36,1612.09 U1_A4.15@10033.36,1531.37 ; v1@10022.26,1656.11 10022.26,1692.77 C49_A4.1@10022.53,1693.04 10024.07,1693.04 10031.89,1700.85 C45_A4.2@10031.89,1743.6 10037.04,1748.75 10037.04,1841.16 10139.75,1943.87 10302.35,1943.87 10321.59,1963.11 10321.59,3209.87 10447.72,3336.01 10447.72,3372.52 10457.1,3381.89 R65_A4.2@10480.91,3381.89
  Bottom Layer w8: v1(10016.67,1648.57) 10019.35,1645.89 10019.35,1631.34 10042.47,1608.22 10068.26,1608.22 10091.32,1585.16 C67_A4.1@10091.32,1581.22
VC13_A1: C37_A1.2 C45_A1.1 C61_A1.1 R61_A1.2 R199_A1.2 U1_A1.13 | length 2313.2
  Top Layer w8: U1_A1.13@3120.88,1531.37 3120.88,1621.97 3125.71,1626.79 v1(3125.71,1653.28) ; v1@3126.44,1651.72 C37_A1.2@3126.44,1688.52 ; R61_A1.2@3585.93,3381.89 3562.12,3381.89 3552.75,3372.52 3552.75,3361.22 3511.27,3319.75 3502.07,3319.75 3385.62,3203.3 3385.62,1956.54 3357.09,1928 3344.96,1928 3342.29,1925.32 3214.06,1925.32 3130.34,1841.59 R199_A1.2@3130.34,1795.9 3130.34,1746.64 C45_A1.1@3127.29,1743.6 3127.29,1696.71 C37_A1.2@3130.96,1693.04 ; C37_A1.2@3126.44,1688.52 C37_A1.2@3130.96,1693.04 ; C37_A1.2@3126.44,1688.52 C37_A1.2@3130.96,1693.04
  Bottom Layer w8: v1(3125.71,1653.28) 3125.71,1652.22 3149.34,1628.6 3161.73,1628.6 3181.34,1608.99 3206.3,1608.99 3213.39,1601.9 3213.39,1587.48 3220.47,1580.39 C61_A1.1@3244.28,1580.39
VC13_A2: C37_A2.2 C45_A2.1 C61_A2.1 R61_A2.2 R199_A2.2 U1_A2.13 | length 2304.1
  Top Layer w8: U1_A2.13@5415.9,1531.37 5415.9,1621.97 5421.46,1627.53 v1(5421.46,1651.49) ; v1@5420.85,1651.11 5421.46,1651.72 5421.46,1688.52 C37_A2.2@5425.98,1693.04 5422.3,1696.71 C45_A2.1@5422.3,1743.6 5425.35,1746.64 R199_A2.2@5425.35,1795.9 5425.35,1841.59 5509.08,1925.32 5637.3,1925.32 5639.98,1928 5652.1,1928 5680.64,1956.54 5680.64,3203.3 5797.09,3319.75 5806.29,3319.75 5847.77,3361.22 5847.77,3372.52 5857.14,3381.89 R61_A2.2@5880.95,3381.89
  Bottom Layer w8: v1(5421.46,1651.49) 5444.35,1628.6 5456.75,1628.6 5476.35,1608.99 5501.32,1608.99 5508.4,1601.9 5508.4,1587.48 5515.49,1580.39 C61_A2.1@5539.3,1580.39
VC13_A3: C37_A3.2 C45_A3.1 C61_A3.1 R61_A3.2 R199_A3.2 U1_A3.13 | length 2304.1
  Top Layer w8: U1_A3.13@7752.5,1534.57 7752.5,1625.18 7758.05,1630.73 v1(7758.05,1654.7) ; v1@7757.45,1654.32 7758.05,1654.93 7758.05,1691.72 C37_A3.2@7762.58,1696.25 7758.9,1699.92 C45_A3.1@7758.9,1746.8 7761.95,1749.85 R199_A3.2@7761.95,1799.11 7761.95,1844.8 7845.68,1928.53 7973.9,1928.53 7976.57,1931.21 7988.7,1931.21 8017.24,1959.75 8017.24,3206.51 8133.68,3322.95 8142.88,3322.95 8184.36,3364.43 8184.36,3375.73 8193.73,3385.1 R61_A3.2@8217.54,3385.1
  Bottom Layer w8: v1(7758.05,1654.7) 7780.95,1631.81 7793.34,1631.81 7812.95,1612.2 7837.91,1612.2 7845,1605.11 7845,1590.69 7852.09,1583.6 C61_A3.1@7875.9,1583.6
VC13_A4: C37_A4.2 C45_A4.1 C61_A4.1 R61_A4.2 R199_A4.2 U1_A4.13 | length 2304.3
  Top Layer w8: U1_A4.13@10072.73,1531.37 10072.73,1621.97 10078.28,1627.53 v1(10078.28,1651.49) ; v1@10077.67,1651.11 10078.28,1651.72 10078.28,1688.52 C37_A4.2@10082.81,1693.04 10079.13,1696.71 C45_A4.1@10079.13,1743.6 10082.18,1746.64 R199_A4.2@10082.18,1795.9 10082.18,1841.59 10165.91,1925.32 10294.13,1925.32 10296.8,1928 10308.93,1928 10337.47,1956.54 10337.47,3203.3 10453.91,3319.75 10463.11,3319.75 10504.59,3361.22 10504.59,3372.52 10513.96,3381.89 R61_A4.2@10537.77,3381.89
  Bottom Layer w8: v1(10078.28,1651.49) 10078.28,1651.15 10100.84,1628.6 10113.57,1628.6 10133.18,1608.99 10158.14,1608.99 10165.23,1601.9 10165.23,1587.48 10172.32,1580.39 C61_A4.1@10196.13,1580.39
VC14_A1: C30_A1.2 C37_A1.1 R51_A1.2 R199_A1.1 R205_A1.2 U1_A1.11 | length 2175.9
  Top Layer w8: U1_A1.11@3160.25,1531.37 3160.25,1605.91 3178.02,1623.67 3178.02,1648.14 3178.47,1648.59 3178.47,1667.54 3178.02,1668 3178.02,1692.85 3178.45,1692.85 3186.45,1700.85 C30_A1.2@3186.45,1743.6 3185.39,1743.6 3177.58,1751.41 R199_A1.1@3177.58,1795.9 3177.58,1844.49 R205_A1.2@3180.18,1847.08 3183.84,1847.08 3199.53,1862.77 3199.53,1863.81 3235.32,1899.61 3303.37,1899.61 3313.22,1909.45 3348.86,1909.45 3350.28,1910.87 3375.07,1910.87 3401.5,1937.29 3401.5,3196.72 3483.75,3278.97 3527.37,3278.97 3609.62,3361.22 3609.62,3372.52 3618.99,3381.89 R51_A1.2@3642.8,3381.89
VC14_A2: C30_A2.2 C37_A2.1 R51_A2.2 R199_A2.1 R205_A2.2 U1_A2.11 | length 2178
  Top Layer w8: U1_A2.11@5455.27,1531.37 5455.27,1605.91 5475.62,1626.26 5475.62,1665.41 5473.03,1668 5473.03,1692.85 5473.46,1692.85 5481.47,1700.85 C30_A2.2@5481.47,1743.6 5480.41,1743.6 5472.6,1751.41 R199_A2.1@5472.6,1795.9 5472.6,1844.49 R205_A2.2@5475.19,1847.08 5478.86,1847.08 5494.55,1862.77 5494.55,1863.81 5530.34,1899.61 5598.39,1899.61 5608.23,1909.45 5643.88,1909.45 5645.29,1910.87 5670.09,1910.87 5696.51,1937.29 5696.51,3196.72 5778.76,3278.97 5822.38,3278.97 5904.63,3361.22 5904.63,3372.52 5914,3381.89 R51_A2.2@5937.82,3381.89 ; C37_A2.1@5473.22,1693.04 C37_A2.1@5473.41,1692.85
VC14_A3: C30_A3.2 C37_A3.1 R51_A3.2 R199_A3.1 R205_A3.2 U1_A3.11 | length 2176.6
  Top Layer w8: U1_A3.11@7791.87,1534.57 7791.87,1609.11 7810.81,1628.06 7810.81,1670.75 7809.63,1671.94 7809.63,1695.62 7810.06,1696.05 7818.06,1704.06 C30_A3.2@7818.06,1746.8 7817,1746.8 7809.19,1754.62 R199_A3.1@7809.19,1799.11 7809.19,1847.7 R205_A3.2@7811.79,1850.29 7815.46,1850.29 7831.14,1865.98 7831.14,1867.02 7866.94,1902.81 7934.99,1902.81 7944.83,1912.66 7980.47,1912.66 7981.89,1914.07 8006.69,1914.07 8033.11,1940.5 8033.11,3199.93 8115.36,3282.18 8158.98,3282.18 8241.23,3364.43 8241.23,3375.73 8250.6,3385.1 R51_A3.2@8274.41,3385.1 ; C37_A3.1@7809.82,1696.25 C37_A3.1@7810.01,1696.05
VC14_A4: C30_A4.2 C37_A4.1 R51_A4.2 R199_A4.1 R205_A4.2 U1_A4.11 | length 2176.9
  Top Layer w8: U1_A4.11@10112.1,1531.37 10112.1,1605.91 10131.13,1624.93 10131.13,1666.73 10129.86,1668 10129.86,1692.85 10130.29,1692.85 10138.29,1700.85 C30_A4.2@10138.29,1743.6 10137.23,1743.6 10129.42,1751.41 R199_A4.1@10129.42,1795.9 10129.42,1844.49 R205_A4.2@10132.02,1847.08 10135.69,1847.08 10151.37,1862.77 10151.37,1863.81 10187.17,1899.61 10255.22,1899.61 10265.06,1909.45 10300.7,1909.45 10302.12,1910.87 10326.92,1910.87 10353.34,1937.29 10353.34,3196.72 10435.59,3278.97 10479.21,3278.97 10561.46,3361.22 10561.46,3372.52 10570.83,3381.89 R51_A4.2@10594.64,3381.89 ; C37_A4.1@10130.05,1693.04 C37_A4.1@10130.24,1692.85
VC15_A1: C22_A1.2 C30_A1.1 R41_A1.2 R200_A1.2 R205_A1.1 U1_A1.9 | length 2312
  Top Layer w8: U1_A1.9@3199.62,1531.37 3199.62,1576.96 3203.16,1580.5 3203.16,1601.09 3227.88,1625.81 3227.88,1653.3 3238.29,1663.71 C22_A1.2@3238.27,1683.78 3235.66,1686.39 C30_A1.1@3235.66,1743.6 ; C30_A1.1@3233.69,1743.6 C30_A1.1@3235.66,1743.6 ; R41_A1.2@3699.67,3381.89 3691.86,3374.08 3691.86,3354.23 3687.77,3350.14 3687.77,3269.86 3699.82,3257.82 3699.82,1927.9 3695.07,1923.16 3409.82,1923.16 3381.65,1894.99 3365.04,1894.99 3363.62,1893.57 3319.79,1893.57 3309.95,1883.73 3285.15,1883.73 3264.97,1863.55 3264.97,1857.15 3254.9,1847.08 R205_A1.1@3227.42,1847.08 3227.42,1803.71 3235.23,1795.9 R200_A1.2@3235.66,1795.9 C30_A1.1@3235.66,1743.6
VC15_A2: C22_A2.2 C30_A2.1 R41_A2.2 R200_A2.2 R205_A2.1 U1_A2.9 | length 2312
  Top Layer w8: U1_A2.9@5494.64,1531.37 5494.64,1576.96 5498.18,1580.5 5498.18,1601.09 5522.9,1625.81 5522.9,1653.3 5533.31,1663.71 C22_A2.2@5533.29,1683.78 5530.68,1686.39 C30_A2.1@5530.68,1743.6 ; C30_A2.1@5528.71,1743.6 C30_A2.1@5530.68,1743.6 ; R41_A2.2@5994.68,3381.89 5986.87,3374.08 5986.87,3354.23 5982.79,3350.14 5982.79,3269.86 5994.83,3257.82 5994.83,1927.9 5990.09,1923.16 5704.83,1923.16 5676.66,1894.99 5660.06,1894.99 5658.64,1893.57 5614.81,1893.57 5604.97,1883.73 5580.17,1883.73 5559.98,1863.55 5559.98,1857.15 5549.92,1847.08 R205_A2.1@5522.44,1847.08 5522.44,1803.71 5530.25,1795.9 R200_A2.2@5530.68,1795.9 C30_A2.1@5530.68,1743.6
VC15_A3: C22_A3.2 C30_A3.1 R41_A3.2 R200_A3.2 R205_A3.1 U1_A3.9 | length 2312
  Top Layer w8: U1_A3.9@7831.24,1534.57 7831.24,1580.17 7834.77,1583.7 7834.77,1604.29 7859.49,1629.01 7859.49,1656.51 7869.91,1666.92 C22_A3.2@7869.89,1686.99 7867.28,1689.6 C30_A3.1@7867.28,1746.8 ; C30_A3.1@7865.31,1746.8 C30_A3.1@7867.28,1746.8 ; R41_A3.2@8331.28,3385.1 8323.47,3377.29 8323.47,3357.43 8319.39,3353.35 8319.39,3273.07 8331.43,3261.03 8331.43,1931.11 8326.69,1926.37 8041.43,1926.37 8013.26,1898.2 7996.65,1898.2 7995.24,1896.78 7951.4,1896.78 7941.56,1886.94 7916.77,1886.94 7896.58,1866.75 7896.58,1860.36 7886.51,1850.29 R205_A3.1@7859.03,1850.29 7859.03,1806.92 7866.84,1799.11 R200_A3.2@7867.28,1799.11 C30_A3.1@7867.28,1746.8
VC15_A4: C22_A4.2 C30_A4.1 R41_A4.2 R200_A4.2 R205_A4.1 U1_A4.9 | length 2312
  Top Layer w8: U1_A4.9@10151.47,1531.37 10151.47,1576.96 10155,1580.5 10155,1601.09 10179.72,1625.81 10179.72,1653.3 10190.14,1663.71 C22_A4.2@10190.12,1683.78 10187.51,1686.39 C30_A4.1@10187.51,1743.6 ; C30_A4.1@10185.54,1743.6 C30_A4.1@10187.51,1743.6 ; R41_A4.2@10651.51,3381.89 10643.7,3374.08 10643.7,3354.23 10639.62,3350.14 10639.62,3269.86 10651.66,3257.82 10651.66,1927.9 10646.92,1923.16 10361.66,1923.16 10333.49,1894.99 10316.88,1894.99 10315.47,1893.57 10271.63,1893.57 10261.79,1883.73 10237,1883.73 10216.81,1863.55 10216.81,1857.15 10206.74,1847.08 R205_A4.1@10179.26,1847.08 10179.26,1803.71 10187.07,1795.9 R200_A4.2@10187.51,1795.9 C30_A4.1@10187.51,1743.6
VC16_A1: C14_A1.2 C22_A1.1 R37_A1.2 R200_A1.1 R206_A1.2 U1_A1.7 | length 2295.9
  Top Layer w8: U1_A1.7@3239,1531.37 3239,1579.25 3247.43,1587.68 3247.43,1590.78 3253.96,1597.3 3253.96,1600.03 3276.03,1622.11 3276.03,1675.97 3283.85,1683.78 C22_A1.1@3285.52,1683.78 ; C22_A1.1@3282.91,1683.78 3282.91,1729.27 C14_A1.2@3290.72,1737.08 ; C14_A1.2@3293.17,1737.08 C14_A1.2@3290.72,1737.08 ; R37_A1.2@3756.54,3381.89 3732.72,3381.89 3724.21,3373.37 3724.21,3267.29 3715.69,3258.78 3715.69,1921.32 3701.65,1907.29 3416.39,1907.29 3388.22,1879.12 3371.62,1879.12 3370.2,1877.7 3326.37,1877.7 3312.48,1863.81 3312.48,1862.77 3296.79,1847.08 3290.72,1847.08 3282.91,1839.27 R200_A1.1@3282.91,1795.9 3282.91,1744.89 C14_A1.2@3290.72,1737.08
VC16_A2: C14_A2.2 C22_A2.1 R37_A2.2 R200_A2.1 R206_A2.2 U1_A2.7 | length 2295.9
  Top Layer w8: U1_A2.7@5534.01,1531.37 5534.01,1579.25 5542.44,1587.68 5542.44,1590.78 5548.97,1597.3 5548.97,1600.03 5571.05,1622.11 5571.05,1675.97 5578.86,1683.78 C22_A2.1@5580.53,1683.78 ; C22_A2.1@5577.92,1683.78 5577.92,1729.27 C14_A2.2@5585.73,1737.08 ; C14_A2.2@5588.19,1737.08 C14_A2.2@5585.73,1737.08 ; R37_A2.2@6051.55,3381.89 6027.74,3381.89 6019.22,3373.37 6019.22,3267.29 6010.71,3258.78 6010.71,1921.32 5996.67,1907.29 5711.41,1907.29 5683.24,1879.12 5666.63,1879.12 5665.22,1877.7 5621.38,1877.7 5607.5,1863.81 5607.5,1862.77 5591.81,1847.08 5585.73,1847.08 5577.92,1839.27 R200_A2.1@5577.92,1795.9 5577.92,1744.89 C14_A2.2@5585.73,1737.08
VC16_A3: C14_A3.2 C22_A3.1 R37_A3.2 R200_A3.1 R206_A3.2 U1_A3.7 | length 2295.9
  Top Layer w8: U1_A3.7@7870.61,1534.57 7870.61,1582.46 7879.04,1590.89 7879.04,1593.98 7885.57,1600.51 7885.57,1603.24 7907.65,1625.32 7907.65,1679.18 7915.46,1686.99 C22_A3.1@7917.13,1686.99 ; C22_A3.1@7914.52,1686.99 7914.52,1732.48 C14_A3.2@7922.33,1740.29 ; C14_A3.2@7924.79,1740.29 C14_A3.2@7922.33,1740.29 ; R37_A3.2@8388.15,3385.1 8364.34,3385.1 8355.82,3376.58 8355.82,3270.5 8347.3,3261.98 8347.3,1924.53 8333.26,1910.49 8048,1910.49 8019.84,1882.33 8003.23,1882.33 8001.81,1880.91 7957.98,1880.91 7944.09,1867.02 7944.09,1865.98 7928.41,1850.29 7922.33,1850.29 7914.52,1842.48 R200_A3.1@7914.52,1799.11 7914.52,1748.1 C14_A3.2@7922.33,1740.29
VC16_A4: C14_A4.2 C22_A4.1 R37_A4.2 R200_A4.1 R206_A4.2 U1_A4.7 | length 2295.9
  Top Layer w8: U1_A4.7@10190.84,1531.37 10190.84,1579.25 10199.27,1587.68 10199.27,1590.78 10205.8,1597.3 10205.8,1600.03 10227.88,1622.11 10227.88,1675.97 10235.69,1683.78 C22_A4.1@10237.36,1683.78 ; C22_A4.1@10234.75,1683.78 10234.75,1729.27 C14_A4.2@10242.56,1737.08 ; C14_A4.2@10245.02,1737.08 C14_A4.2@10242.56,1737.08 ; R37_A4.2@10708.38,3381.89 10684.57,3381.89 10676.05,3373.37 10676.05,3267.29 10667.53,3258.78 10667.53,1921.32 10653.49,1907.29 10368.23,1907.29 10340.07,1879.12 10323.46,1879.12 10322.04,1877.7 10278.21,1877.7 10264.32,1863.81 10264.32,1862.77 10248.64,1847.08 10242.56,1847.08 10234.75,1839.27 R200_A4.1@10234.75,1795.9 10234.75,1744.89 C14_A4.2@10242.56,1737.08
VC17_A1: C7_A1.2 C14_A1.1 R26_A1.2 R201_A1.2 R206_A1.1 U1_A1.5 | length 2290.6
  Top Layer w8: U1_A1.5@3278.37,1531.37 3280.27,1533.27 3280.27,1572.8 3282.08,1574.61 3282.08,1577.7 3287.7,1583.32 3287.7,1586.05 3315.79,1614.13 3315.79,1616.67 3337.42,1638.3 3337.42,1641.53 3345.82,1649.93 3345.82,1683.81 3346.22,1683.81 C7_A1.2@3346.47,1683.55 ; C14_A1.1@3340.42,1737.08 3346.01,1742.67 3346.01,1786.96 3340.1,1792.86 R206_A1.1@3340.1,1847.08 3365.62,1847.08 3371.24,1852.7 3371.24,1856.29 3378.19,1863.24 3394.8,1863.24 3422.97,1891.41 3720.38,1891.41 3731.56,1902.6 3731.56,2848.54 3742.7,2859.67 3741.25,2861.12 3741.25,3210.54 3768.33,3237.62 3768.33,3262.03 3780.22,3273.92 3780.22,3372.52 3789.59,3381.89 R26_A1.2@3813.4,3381.89 ; C7_A1.2@3346.01,1683.55 C14_A1.1@3346.01,1733.32
VC17_A2: C7_A2.2 C14_A2.1 R26_A2.2 R201_A2.2 R206_A2.1 U1_A2.5 | length 2290.6
  Top Layer w8: U1_A2.5@5573.38,1531.37 5575.29,1533.27 5575.29,1572.8 5577.1,1574.61 5577.1,1577.7 5582.72,1583.32 5582.72,1586.05 5610.8,1614.13 5610.8,1616.67 5632.44,1638.3 5632.44,1641.53 5640.83,1649.93 5640.83,1683.81 5641.23,1683.81 C7_A2.2@5641.49,1683.55 ; C14_A2.1@5635.43,1737.08 5641.02,1742.67 5641.02,1786.96 5635.12,1792.86 R206_A2.1@5635.12,1847.08 5660.63,1847.08 5666.25,1852.7 5666.25,1856.29 5673.21,1863.24 5689.81,1863.24 5717.98,1891.41 6015.39,1891.41 6026.58,1902.6 6026.58,2848.54 6037.71,2859.67 6036.26,2861.12 6036.26,3210.54 6063.34,3237.62 6063.34,3262.03 6075.24,3273.92 6075.24,3372.52 6084.61,3381.89 R26_A2.2@6108.42,3381.89 ; C7_A2.2@5641.02,1683.55 C14_A2.1@5641.02,1733.32
VC17_A3: C7_A3.2 C14_A3.1 R26_A3.2 R201_A3.2 R206_A3.1 U1_A3.5 | length 2290.6
  Top Layer w8: U1_A3.5@7909.98,1534.57 7911.88,1536.48 7911.88,1576.01 7913.69,1577.82 7913.69,1580.91 7919.32,1586.53 7919.32,1589.26 7947.4,1617.34 7947.4,1619.88 7969.03,1641.51 7969.03,1644.74 7977.43,1653.14 7977.43,1687.01 7977.83,1687.01 C7_A3.2@7978.09,1686.76 ; C14_A3.1@7972.03,1740.29 7977.62,1745.87 7977.62,1790.16 7971.71,1796.07 R206_A3.1@7971.71,1850.29 7997.23,1850.29 8002.85,1855.91 8002.85,1859.5 8009.8,1866.45 8026.41,1866.45 8054.58,1894.62 8351.99,1894.62 8363.18,1905.81 8363.18,2851.75 8374.31,2862.88 8372.86,2864.33 8372.86,3213.75 8399.94,3240.83 8399.94,3265.24 8411.83,3277.13 8411.83,3375.73 8421.2,3385.1 R26_A3.2@8445.02,3385.1 ; C7_A3.2@7977.62,1686.76 C14_A3.1@7977.62,1736.53
VC17_A4: C7_A4.2 C14_A4.1 R26_A4.2 R201_A4.2 R206_A4.1 U1_A4.5 | length 2290.6
  Top Layer w8: U1_A4.5@10230.21,1531.37 10232.11,1533.27 10232.11,1572.8 10233.92,1574.61 10233.92,1577.7 10239.55,1583.32 10239.55,1586.05 10267.63,1614.13 10267.63,1616.67 10289.26,1638.3 10289.26,1641.53 10297.66,1649.93 10297.66,1683.81 10298.06,1683.81 C7_A4.2@10298.32,1683.55 ; C14_A4.1@10292.26,1737.08 10297.85,1742.67 10297.85,1786.96 10291.94,1792.86 R206_A4.1@10291.94,1847.08 10317.46,1847.08 10323.08,1852.7 10323.08,1856.29 10330.03,1863.24 10346.64,1863.24 10374.81,1891.41 10672.22,1891.41 10683.41,1902.6 10683.41,2848.54 10694.54,2859.67 10693.09,2861.12 10693.09,3210.54 10720.17,3237.62 10720.17,3262.03 10732.06,3273.92 10732.06,3372.52 10741.43,3381.89 R26_A4.2@10765.25,3381.89 ; C7_A4.2@10297.85,1683.55 C14_A4.1@10297.85,1733.32
VC18_A1: C7_A1.1 D1_A1.2 R19_A1.2 R201_A1.1 R207_A1.2 U1_A1.3 | length 2622.7
  Top Layer w8: U1_A1.3@3317.74,1531.37 3319.64,1533.27 3319.64,1567.53 3321.45,1569.35 3321.45,1572.07 3340.02,1590.64 3345.23,1590.64 3366.92,1612.33 3383.89,1612.33 3393.06,1621.5 C7_A1.1@3393.06,1683.81 ; R201_A1.1@3392.57,1787.63 R201_A1.1@3398.19,1793.25 ; C7_A1.1@3393.46,1692.33 3434.48,1692.33 v1(3434.69,1692.54) ; R19_A1.2@3870.27,3381.89 3846.46,3381.89 3837.09,3372.52 3837.09,3281.15 3759.09,3203.15 3759.09,2850.84 3747.44,2839.18 3747.44,1896.02 3726.95,1875.54 3704.06,1875.54 3698.21,1869.69 3599.23,1869.69 3598.15,1870.77 3424.77,1870.77 3417.82,1863.81 3417.82,1854.58 3402.8,1839.56 R207_A1.2@3398.86,1839.56 3398.19,1838.9 R201_A1.1@3398.19,1793.25 ; C7_A1.1@3393.72,1683.55 C7_A1.1@3393.72,1690.71 ; C7_A1.1@3393.72,1683.55 C7_A1.1@3393.72,1690.71 ; C7_A1.1@3393.72,1683.55 C7_A1.1@3393.72,1690.71 ; C7_A1.1@3393.72,1690.71 3392.96,1690.71 3392.3,1691.36 3392.3,1787.36 R201_A1.1@3398.19,1793.25
  Bottom Layer w20: v1(3434.69,1692.54) 3470.29,1656.93 3471.21,1656.93 3472.16,1655.98 3548.41,1655.98 3605.09,1599.3 3645.66,1599.3 D1_A1.2@3662.74,1582.22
